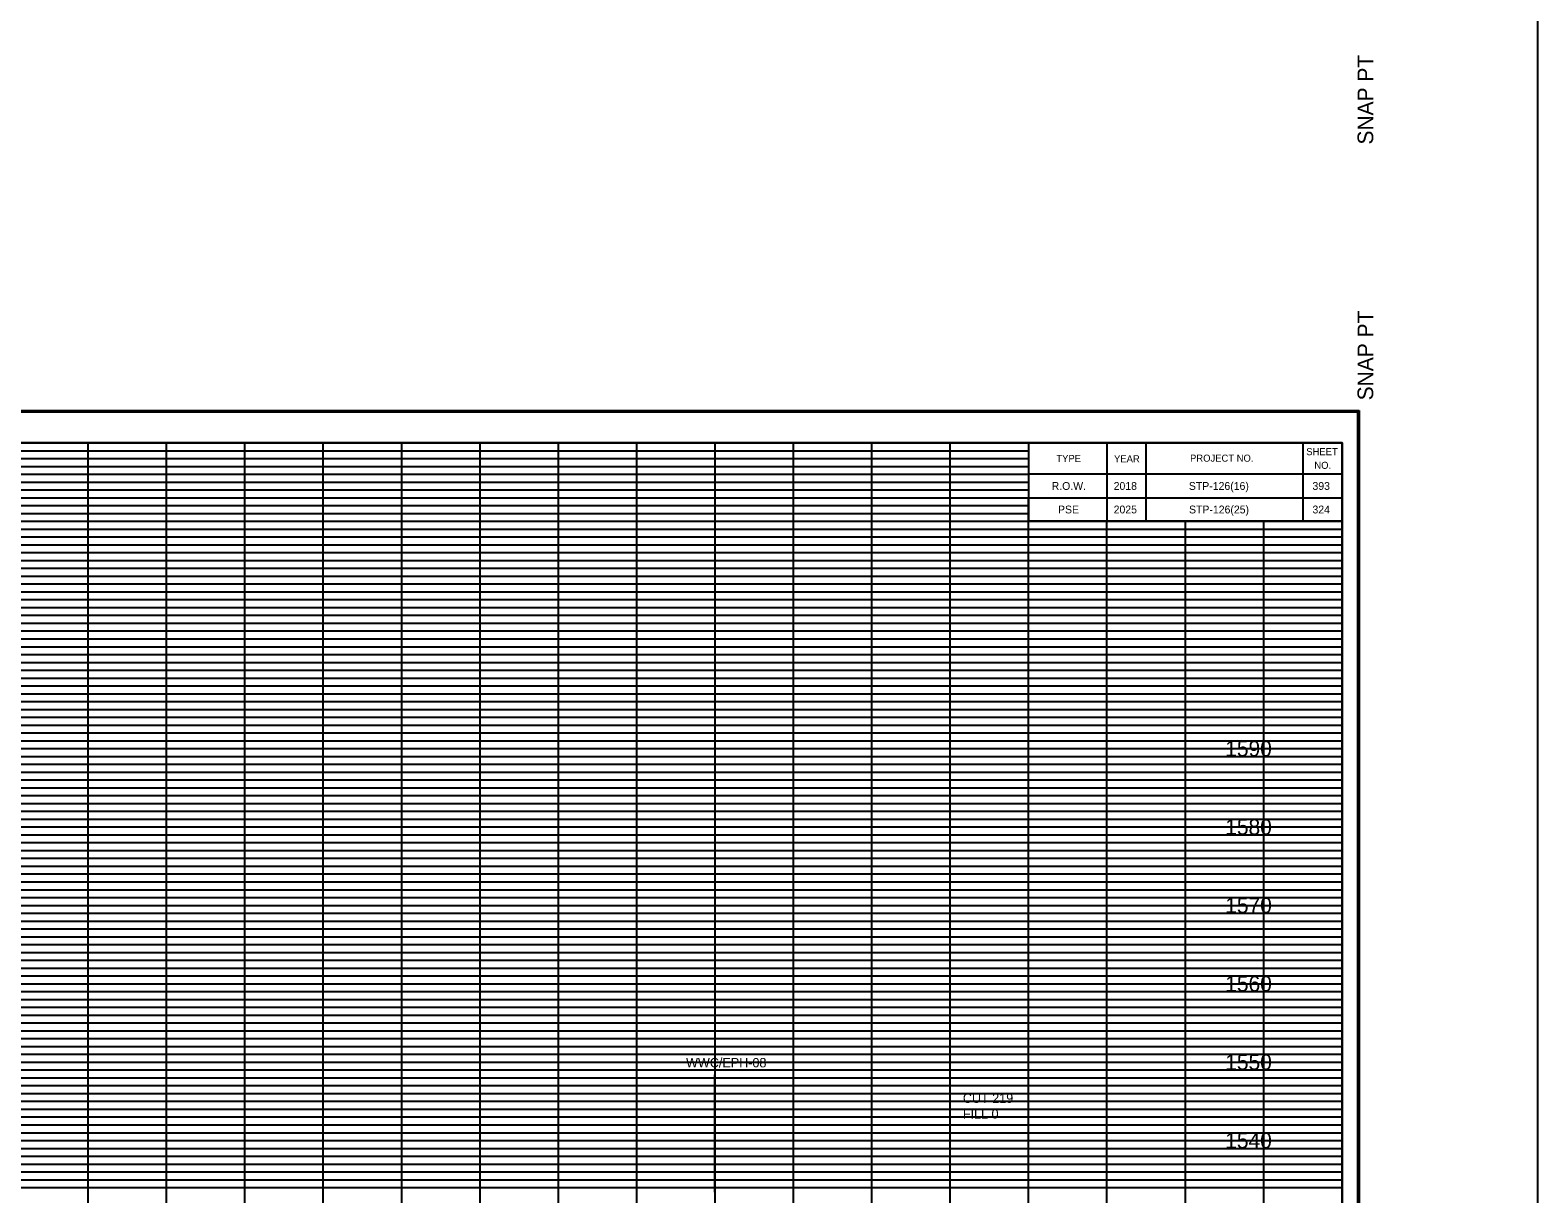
# Model space of a CAD drawing. Extents: x 955 to 1375, y 1248 to 3657.
# Drawn here: x 1152.6 to 1345, y 1654.2 to 1802.7 of the extents above; entities that cross this region are included whole.
import ezdxf

# ---------------------------------------------------------------- set-up
doc = ezdxf.new("R2010")
doc.units = 0
for name, color, linetype in [('DESIGN - SCRATCH - User 1', 7, 'Continuous'), ('DESIGN - SHEET - Corner Text', 7, 'Continuous'), ('DESIGN - SHEET - Light Grid', 7, 'Continuous'), ('DESIGN - SHEET - Linework', 7, 'Continuous'), ('DESIGN - SHEET - Plot Shape', 7, 'Continuous'), ('DESIGN - TYPICAL - Text', 7, 'Continuous'), ('DESIGN - UTILITIES - Cable (Overhead) with Text', 7, 'Continuous'), ('SURVEY - NON-TRANSPORTATION - Features', 7, 'Continuous'), ('SURVEY - NON-TRANSPORTATION - Features Text', 7, 'Continuous')]:
    doc.layers.add(name, color=color, linetype=linetype)

# ---------------------------------------------------------------- blocks, each defined once
blk = doc.blocks.new('XSTSHT')
at = {"layer": 'DESIGN - SCRATCH - User 1'}
for p, q in [((28.5, 20.45), (28.5, 20.45)), ((29.24, 20.45), (29.24, 20.45)), ((30.49, 20.45), (30.49, 20.45)), ((31.74, 20.45), (31.74, 20.45)), ((28.5, 20.15), (28.5, 20.15)), ((29.24, 20.15), (29.24, 20.15)), ((30.49, 20.15), (30.49, 20.15)), ((31.74, 20.15), (31.74, 20.15))]:
    blk.add_line(p, q, dxfattribs=at)
at = {"layer": 'DESIGN - SHEET - Light Grid'}
for p, q in [((8, 20.9), (16, 20.9)), ((8, 20.8), (16, 20.8)), ((16, 20.9), (24, 20.9)), ((16, 20.8), (24, 20.8)), ((24, 20.9), (28, 20.9)), ((24, 20.8), (28, 20.8)), ((8, 20.7), (16, 20.7)), ((8, 20.6), (16, 20.6)), ((16, 20.7), (24, 20.7)), ((16, 20.6), (24, 20.6)), ((24, 20.7), (28, 20.7)), ((24, 20.6), (28, 20.6)), ((8, 20.5), (16, 20.5)), ((8, 20.4), (16, 20.4)), ((16, 20.5), (24, 20.5)), ((16, 20.4), (24, 20.4)), ((24, 20.5), (28, 20.5)), ((24, 20.4), (28, 20.4)), ((8, 20.3), (16, 20.3)), ((16, 20.3), (24, 20.3)), ((24, 20.3), (28, 20.3)), ((8, 20.2), (16, 20.2)), ((8, 20.1), (16, 20.1)), ((16, 20.2), (24, 20.2)), ((16, 20.1), (24, 20.1)), ((24, 20.2), (28, 20.2)), ((24, 20.1), (28, 20.1)), ((8, 19.9), (16, 19.9)), ((16, 19.9), (24, 19.9)), ((24, 19.9), (32, 19.9)), ((8, 19.8), (16, 19.8)), ((8, 19.7), (16, 19.7)), ((16, 19.8), (24, 19.8)), ((16, 19.7), (24, 19.7)), ((24, 19.8), (32, 19.8)), ((24, 19.7), (32, 19.7)), ((8, 19.6), (16, 19.6)), ((8, 19.5), (16, 19.5)), ((16, 19.6), (24, 19.6)), ((16, 19.5), (24, 19.5)), ((24, 19.6), (32, 19.6)), ((24, 19.5), (32, 19.5)), ((8, 19.4), (16, 19.4)), ((8, 19.3), (16, 19.3)), ((16, 19.4), (24, 19.4)), ((16, 19.3), (24, 19.3)), ((24, 19.4), (32, 19.4)), ((24, 19.3), (32, 19.3)), ((8, 19.2), (16, 19.2)), ((8, 19.1), (16, 19.1)), ((16, 19.2), (24, 19.2)), ((16, 19.1), (24, 19.1)), ((24, 19.2), (32, 19.2)), ((24, 19.1), (32, 19.1)), ((8, 18.9), (16, 18.9)), ((16, 18.9), (24, 18.9)), ((24, 18.9), (32, 18.9)), ((8, 18.8), (16, 18.8)), ((8, 18.7), (16, 18.7)), ((16, 18.8), (24, 18.8)), ((16, 18.7), (24, 18.7)), ((24, 18.8), (32, 18.8)), ((24, 18.7), (32, 18.7)), ((8, 18.6), (16, 18.6)), ((8, 18.5), (16, 18.5)), ((16, 18.6), (24, 18.6)), ((16, 18.5), (24, 18.5)), ((24, 18.6), (32, 18.6)), ((24, 18.5), (32, 18.5)), ((8, 18.4), (16, 18.4)), ((8, 18.3), (16, 18.3)), ((16, 18.4), (24, 18.4)), ((16, 18.3), (24, 18.3)), ((24, 18.4), (32, 18.4)), ((24, 18.3), (32, 18.3)), ((8, 18.2), (16, 18.2)), ((8, 18.1), (16, 18.1)), ((16, 18.2), (24, 18.2)), ((16, 18.1), (24, 18.1)), ((24, 18.2), (32, 18.2)), ((24, 18.1), (32, 18.1)), ((8, 17.9), (16, 17.9)), ((16, 17.9), (24, 17.9)), ((24, 17.9), (32, 17.9)), ((8, 17.8), (16, 17.8)), ((8, 17.7), (16, 17.7)), ((16, 17.8), (24, 17.8)), ((16, 17.7), (24, 17.7)), ((24, 17.8), (32, 17.8)), ((24, 17.7), (32, 17.7)), ((8, 17.6), (16, 17.6)), ((16, 17.6), (24, 17.6)), ((24, 17.6), (32, 17.6)), ((8, 17.5), (16, 17.5)), ((8, 17.4), (16, 17.4)), ((16, 17.5), (24, 17.5)), ((16, 17.4), (24, 17.4)), ((24, 17.5), (32, 17.5)), ((24, 17.4), (32, 17.4)), ((8, 17.3), (16, 17.3)), ((8, 17.2), (16, 17.2)), ((16, 17.3), (24, 17.3)), ((16, 17.2), (24, 17.2)), ((24, 17.3), (32, 17.3)), ((24, 17.2), (32, 17.2)), ((8, 17.1), (16, 17.1)), ((16, 17.1), (24, 17.1)), ((24, 17.1), (32, 17.1)), ((8, 16.9), (16, 16.9)), ((8, 16.8), (16, 16.8)), ((16, 16.9), (24, 16.9)), ((16, 16.8), (24, 16.8)), ((24, 16.9), (32, 16.9)), ((24, 16.8), (32, 16.8)), ((8, 16.7), (16, 16.7)), ((8, 16.6), (16, 16.6)), ((16, 16.7), (24, 16.7)), ((16, 16.6), (24, 16.6)), ((24, 16.7), (32, 16.7)), ((24, 16.6), (32, 16.6)), ((8, 16.5), (16, 16.5)), ((8, 16.4), (16, 16.4)), ((16, 16.5), (24, 16.5)), ((16, 16.4), (24, 16.4)), ((24, 16.5), (32, 16.5)), ((24, 16.4), (32, 16.4)), ((8, 16.3), (16, 16.3)), ((8, 16.2), (16, 16.2)), ((16, 16.3), (24, 16.3)), ((16, 16.2), (24, 16.2)), ((24, 16.3), (32, 16.3)), ((24, 16.2), (32, 16.2)), ((8, 16.1), (16, 16.1)), ((16, 16.1), (24, 16.1)), ((24, 16.1), (32, 16.1)), ((8, 15.9), (16, 15.9)), ((8, 15.8), (16, 15.8)), ((16, 15.9), (24, 15.9)), ((16, 15.8), (24, 15.8)), ((24, 15.9), (32, 15.9)), ((24, 15.8), (32, 15.8)), ((8, 15.7), (16, 15.7)), ((8, 15.6), (16, 15.6)), ((16, 15.7), (24, 15.7)), ((16, 15.6), (24, 15.6)), ((24, 15.7), (32, 15.7)), ((24, 15.6), (32, 15.6)), ((8, 15.5), (16, 15.5)), ((8, 15.4), (16, 15.4)), ((16, 15.5), (24, 15.5)), ((16, 15.4), (24, 15.4)), ((24, 15.5), (32, 15.5)), ((24, 15.4), (32, 15.4)), ((8, 15.3), (16, 15.3)), ((8, 15.2), (16, 15.2)), ((16, 15.3), (24, 15.3)), ((16, 15.2), (24, 15.2)), ((24, 15.3), (32, 15.3)), ((24, 15.2), (32, 15.2)), ((8, 15.1), (16, 15.1)), ((16, 15.1), (24, 15.1)), ((24, 15.1), (32, 15.1)), ((8, 14.9), (16, 14.9)), ((16, 14.9), (24, 14.9)), ((24, 14.9), (32, 14.9)), ((8, 14.8), (16, 14.8)), ((8, 14.7), (16, 14.7)), ((16, 14.8), (24, 14.8)), ((16, 14.7), (24, 14.7)), ((24, 14.8), (32, 14.8)), ((24, 14.7), (32, 14.7)), ((8, 14.6), (16, 14.6)), ((8, 14.5), (16, 14.5)), ((16, 14.6), (24, 14.6)), ((16, 14.5), (24, 14.5)), ((24, 14.6), (32, 14.6)), ((24, 14.5), (32, 14.5)), ((8, 14.4), (16, 14.4)), ((8, 14.3), (16, 14.3)), ((16, 14.4), (24, 14.4)), ((16, 14.3), (24, 14.3)), ((24, 14.4), (32, 14.4)), ((24, 14.3), (32, 14.3)), ((8, 14.2), (16, 14.2)), ((8, 14.1), (16, 14.1)), ((16, 14.2), (24, 14.2)), ((16, 14.1), (24, 14.1)), ((24, 14.2), (32, 14.2)), ((24, 14.1), (32, 14.1)), ((8, 13.9), (16, 13.9)), ((16, 13.9), (24, 13.9)), ((24, 13.9), (32, 13.9)), ((8, 13.8), (16, 13.8)), ((8, 13.7), (16, 13.7)), ((16, 13.8), (24, 13.8)), ((16, 13.7), (24, 13.7)), ((24, 13.8), (32, 13.8)), ((24, 13.7), (32, 13.7)), ((8, 13.6), (16, 13.6)), ((8, 13.5), (16, 13.5)), ((16, 13.6), (24, 13.6)), ((16, 13.5), (24, 13.5)), ((24, 13.6), (32, 13.6)), ((24, 13.5), (32, 13.5)), ((8, 13.4), (16, 13.4)), ((8, 13.3), (16, 13.3)), ((16, 13.4), (24, 13.4)), ((16, 13.3), (24, 13.3)), ((24, 13.4), (32, 13.4)), ((24, 13.3), (32, 13.3)), ((8, 13.2), (16, 13.2)), ((8, 13.1), (16, 13.1)), ((16, 13.2), (24, 13.2)), ((16, 13.1), (24, 13.1)), ((24, 13.2), (32, 13.2)), ((24, 13.1), (32, 13.1)), ((8, 12.9), (16, 12.9)), ((16, 12.9), (24, 12.9)), ((24, 12.9), (32, 12.9)), ((8, 12.8), (16, 12.8)), ((8, 12.7), (16, 12.7)), ((16, 12.8), (24, 12.8)), ((16, 12.7), (24, 12.7)), ((24, 12.8), (32, 12.8)), ((24, 12.7), (32, 12.7)), ((8, 12.6), (16, 12.6)), ((16, 12.6), (24, 12.6)), ((24, 12.6), (32, 12.6)), ((8, 12.5), (16, 12.5)), ((8, 12.4), (16, 12.4)), ((16, 12.5), (24, 12.5)), ((16, 12.4), (24, 12.4)), ((24, 12.5), (32, 12.5)), ((24, 12.4), (32, 12.4)), ((8, 12.3), (16, 12.3)), ((8, 12.2), (16, 12.2)), ((16, 12.3), (24, 12.3)), ((16, 12.2), (24, 12.2)), ((24, 12.3), (32, 12.3)), ((24, 12.2), (32, 12.2)), ((8, 12.1), (16, 12.1)), ((16, 12.1), (24, 12.1)), ((24, 12.1), (32, 12.1)), ((8, 11.9), (16, 11.9)), ((8, 11.8), (16, 11.8)), ((16, 11.9), (24, 11.9)), ((16, 11.8), (24, 11.8)), ((24, 11.9), (32, 11.9)), ((24, 11.8), (32, 11.8)), ((8, 11.7), (16, 11.7)), ((8, 11.6), (16, 11.6)), ((16, 11.7), (24, 11.7)), ((16, 11.6), (24, 11.6)), ((24, 11.7), (32, 11.7)), ((24, 11.6), (32, 11.6)), ((8, 11.5), (16, 11.5)), ((16, 11.5), (24, 11.5)), ((24, 11.5), (32, 11.5))]:
    blk.add_line(p, q, dxfattribs=at)
at = {"layer": 'DESIGN - SHEET - Linework'}
for p, q in [((-1.823, 21.414), (32.217, 21.414)), ((32.217, 21.414), (32.217, -0.414)), ((16, 0), (16, 21)), ((17, 0), (17, 21)), ((18, 0), (18, 21)), ((19, 0), (19, 21)), ((20, 0), (20, 21)), ((21, 0), (21, 21)), ((22, 0), (22, 21)), ((23, 0), (23, 21)), ((24, 0), (24, 21)), ((25, 0), (25, 21)), ((26, 0), (26, 21)), ((27, 0), (27, 21)), ((0, 20), (28, 20)), ((28, 0), (28, 20)), ((29, 0), (29, 20)), ((30, 0), (30, 20)), ((31, 0), (31, 20)), ((0, 19), (32, 19)), ((0, 18), (32, 18)), ((0, 17), (32, 17)), ((0, 16), (32, 16)), ((0, 15), (32, 15)), ((0, 14), (32, 14)), ((0, 13), (32, 13)), ((0, 12), (32, 12))]:
    blk.add_line(p, q, dxfattribs=at)
for points in [[(0, 21), (0, 0), (32, 0), (32, 21), (0, 21)], [(28, 21), (28, 20), (32, 20), (32, 21), (31.5, 21), (31.5, 20), (29.5, 20), (29.5, 21), (29, 21), (29, 20), (32, 20), (28, 20), (28, 20.3), (32, 20.3), (32, 20.6), (28, 20.6)]]:
    blk.add_lwpolyline(points, dxfattribs=at)
at = {"layer": 'DESIGN - SHEET - Plot Shape'}
for points in [[(-1.803, 21.394), (32.197, 21.394), (32.197, -0.394), (-1.803, -0.394)], [(-0.85, 21), (32, 21), (32, -0.25), (-0.85, -0.25)]]:
    blk.add_lwpolyline(points, close=True, dxfattribs=at)
at = {"layer": 'DESIGN - SHEET - Corner Text'}
for s, p in [('  SNAP PT', (32.397, 21.394)), ('SNAP PT  ', (32.397, -2.194))]:
    blk.add_text(s, height=0.2, rotation=90, dxfattribs=at).set_placement(p)
for s, p in [('TYPE', (28.354, 20.756)), ('YEAR', (29.09, 20.752)), ('PROJECT NO.', (30.06, 20.76)), ('SHEET', (31.543, 20.843)), ('NO.', (31.646, 20.669))]:
    blk.add_text(s, height=0.09, dxfattribs=at).set_placement(p)

msp = doc.modelspace()

# ---------------------------------------------------------------- linework, layer by layer
at = {"layer": 'DESIGN - SHEET - Plot Shape'}
msp.add_lwpolyline([(991.5, 1537.5), (1320, 1537.5), (1320, 1750), (991.5, 1750)], close=True, dxfattribs=at)
at = {"layer": 'SURVEY - NON-TRANSPORTATION - Features'}
msp.add_line((1239.97, 1654.39), (1239.97, 1669.39), dxfattribs=at)
at = {"layer": 'SURVEY - NON-TRANSPORTATION - Features Text'}
msp.add_lwpolyline([(955.41, 1505.76), (1344.98, 1505.76), (1344.98, 3398.01), (955.41, 3398.01)], close=True, dxfattribs=at)

# ---------------------------------------------------------------- block references
at = {"layer": 'DESIGN - UTILITIES - Cable (Overhead) with Text', "xscale": 10, "yscale": 10}
for p in [(1000, 1810), (1000, 1540)]:
    msp.add_blockref('XSTSHT', p, dxfattribs=at)

# ---------------------------------------------------------------- texts
at = {"layer": 'DESIGN - SHEET - Corner Text'}
for s, p in [('R.O.W.', (1282.94, 1744)), ('2018', (1290.85, 1744)), ('STP-126(16)', (1300.45, 1744)), ('393', (1316.22, 1744)), ('PSE', (1283.75, 1741)), ('2025', (1290.85, 1741)), ('STP-126(25)', (1300.47, 1741)), ('324', (1316.22, 1741))]:
    msp.add_text(s, height=1, dxfattribs=at).set_placement(p)
at = {"layer": 'DESIGN - TYPICAL - Text'}
for s, height, p in [('     1590     ', 2, (1301.37, 1710)), ('     1580     ', 2, (1301.37, 1700)), ('     1570     ', 2, (1301.37, 1690)), ('     1560     ', 2, (1301.37, 1680)), ('     1550     ', 2, (1301.37, 1670)), ('CUT 219', 1.2, (1271.61, 1665.8)), ('FILL 0', 1.2, (1271.61, 1663.8)), ('     1540     ', 2, (1301.37, 1660))]:
    msp.add_text(s, height=height, dxfattribs=at).set_placement(p)
at = {"layer": 'SURVEY - NON-TRANSPORTATION - Features'}
msp.add_text('WWC/EPH-08', height=1.2, dxfattribs=at).set_placement((1236.29, 1670.33))

doc.saveas('drawing.dxf')
